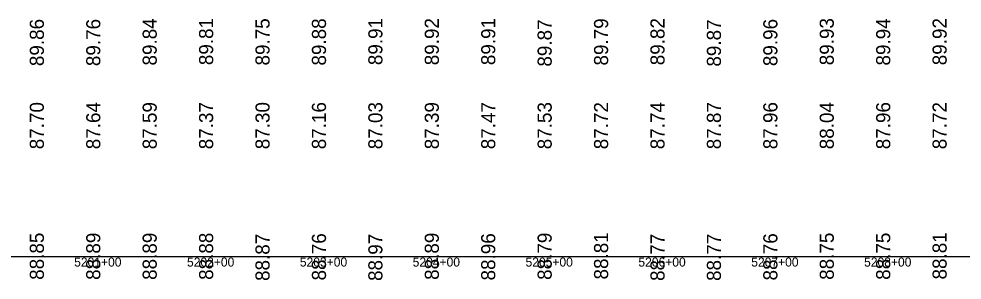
# Model space of a CAD drawing. Extents: x 2147288 to 2220488, y 740833 to 759333.
# Drawn here: x 2202408 to 2203244, y 750062 to 750294 of the extents above; entities that cross this region are included whole.
import ezdxf

# ---------------------------------------------------------------- set-up
doc = ezdxf.new("R2010")
doc.units = 0
for name, color, linetype in [('RD_DDB_Profile_EX', 7, 'Continuous'), ('RD_DDB_StaTX', 7, 'Continuous'), ('RD_DDB_StripGrade', 7, 'Continuous'), ('RD_GPK_Profile_Cell', 7, 'Continuous')]:
    doc.layers.add(name, color=color, linetype=linetype)

msp = doc.modelspace()

# ---------------------------------------------------------------- linework, layer by layer
at = {"layer": 'RD_GPK_Profile_Cell'}
msp.add_line((2198888.28, 750083.43), (2220488.28, 750083.43), dxfattribs=at)

# ---------------------------------------------------------------- texts
at = {"layer": 'RD_DDB_Profile_EX'}
for s, p in [('89.86', (2202430.08, 750252.13)), ('89.76', (2202480.08, 750252.13)), ('89.84', (2202530.08, 750252.66)), ('89.81', (2202580.08, 750253)), ('89.75', (2202630.08, 750252.69)), ('89.88', (2202680.08, 750252.64)), ('89.91', (2202730.08, 750253)), ('89.92', (2202780.08, 750252.89)), ('89.91', (2202830.08, 750253)), ('89.87', (2202880.08, 750251.67)), ('89.79', (2202930.08, 750252.64)), ('89.82', (2202980.08, 750252.89)), ('89.87', (2203030.08, 750251.67)), ('89.96', (2203080.08, 750252.13)), ('89.93', (2203130.08, 750252.89)), ('89.94', (2203180.08, 750252.66)), ('89.92', (2203230.08, 750252.89)), ('88.85', (2202430.08, 750062.69)), ('88.89', (2202480.08, 750062.64)), ('88.89', (2202530.08, 750062.64)), ('88.88', (2202580.08, 750062.64)), ('88.87', (2202630.08, 750061.67)), ('88.76', (2202680.08, 750062.13)), ('88.97', (2202730.08, 750061.67)), ('88.89', (2202780.08, 750062.64)), ('88.96', (2202830.08, 750062.13)), ('88.79', (2202880.08, 750062.64)), ('88.81', (2202930.08, 750063)), ('88.77', (2202980.08, 750061.67)), ('88.77', (2203030.08, 750061.67)), ('88.76', (2203080.08, 750062.13)), ('88.75', (2203130.08, 750062.69)), ('88.75', (2203180.08, 750062.69)), ('88.81', (2203230.08, 750063))]:
    msp.add_text(s, height=12.5, rotation=90, dxfattribs=at).set_placement(p)
at = {"layer": 'RD_DDB_StaTX'}
for s, p in [('5201+00', (2202456.88, 750074.43)), ('5201+00', (2202456.88, 750074.43)), ('5201+00', (2202456.88, 750074.43)), ('5202+00', (2202556.88, 750074.43)), ('5202+00', (2202556.88, 750074.43)), ('5202+00', (2202556.88, 750074.43)), ('5203+00', (2202656.88, 750074.43)), ('5203+00', (2202656.88, 750074.43)), ('5203+00', (2202656.88, 750074.43)), ('5204+00', (2202756.88, 750074.43)), ('5204+00', (2202756.88, 750074.43)), ('5204+00', (2202756.88, 750074.43)), ('5205+00', (2202856.88, 750074.43)), ('5205+00', (2202856.88, 750074.43)), ('5205+00', (2202856.88, 750074.43)), ('5206+00', (2202956.88, 750074.43)), ('5206+00', (2202956.88, 750074.43)), ('5206+00', (2202956.88, 750074.43)), ('5207+00', (2203056.88, 750074.43)), ('5207+00', (2203056.88, 750074.43)), ('5207+00', (2203056.88, 750074.43)), ('5208+00', (2203156.88, 750074.43)), ('5208+00', (2203156.88, 750074.43)), ('5208+00', (2203156.88, 750074.43))]:
    msp.add_text(s, height=8, dxfattribs=at).set_placement(p)
at = {"layer": 'RD_DDB_StripGrade'}
for s, p in [('87.70', (2202430.08, 750178.43)), ('87.64', (2202480.08, 750178.43)), ('87.59', (2202530.08, 750178.43)), ('87.37', (2202580.08, 750178.43)), ('87.30', (2202630.08, 750178.43)), ('87.16', (2202680.08, 750178.43)), ('87.03', (2202730.08, 750178.43)), ('87.39', (2202780.08, 750178.43)), ('87.47', (2202830.08, 750178.43)), ('87.53', (2202880.08, 750178.43)), ('87.72', (2202930.08, 750178.43)), ('87.74', (2202980.08, 750178.43)), ('87.87', (2203030.08, 750178.43)), ('87.96', (2203080.08, 750178.43)), ('88.04', (2203130.08, 750178.43)), ('87.96', (2203180.08, 750178.43)), ('87.72', (2203230.08, 750178.43))]:
    msp.add_text(s, height=12.5, rotation=90, dxfattribs=at).set_placement(p)

doc.saveas('drawing.dxf')
